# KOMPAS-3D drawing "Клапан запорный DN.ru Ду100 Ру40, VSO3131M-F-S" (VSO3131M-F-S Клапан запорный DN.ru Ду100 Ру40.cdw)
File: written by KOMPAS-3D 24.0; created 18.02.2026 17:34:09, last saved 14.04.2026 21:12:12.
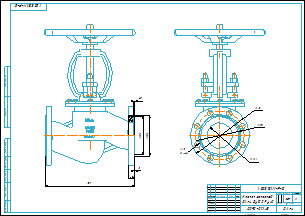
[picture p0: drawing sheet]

Document properties: Автор: R2D2; Форматы листов документа: A2; Полное имя файла: VSO3131M-F-S Клапан запорный DN.ru Ду100 Ру40.m3d; Масса: 36.7; Наименование: Клапан запорный DN.ru Ду100 Ру40; Количество листов документа: 1; Примечание: D090-02145

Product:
- Part/product: Клапан запорный DN.ru Ду100 Ру40  | designation VSO3131M-F-S
    Масса: 36.7
    Раздел спецификации: Прочие изделия
    Примечание: D090-02145

Views: Вид 1, Местный разрез 1, Спереди, Проекционный вид 2
Referenced files in E:\Работа\Зайцев\VSO3131M-F-S Клапан запорный DN.ru Ду15-100 Ру40\DN100\: VSO3131M-F-S Клапан запорный DN.ru Ду100 Ру40.m3d
Referenced files in E:\Работа\Зайцев\VSO3131M-F-S Клапан запорный DN.ru Ду15-100 Ру40\DN50\: VSO3131M-F-S Клапан запорный DN.ru Ду50 Ру40.m3d
Referenced files in E:\Работа\Зайцев\Для компаса\: чертеж DN.ru А3.cdt
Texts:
  VSO3131M-F-S
  чертеж DN.ru А3.cdt
  Клапан запорный
  DN.ru Ду100 Ру40
  Клапан запорный DN.ru Ду100 Ру40
  VSO3131M-F-S Клапан запорный DN.ru Ду100 Ру40
Dimensions and other numbers on the sheet: 0; 3; 2; 4; 350; 24; 160; 150; 4,5; 230; 190; 100; 23; 8 отв.; 1:2; 1; 36,7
